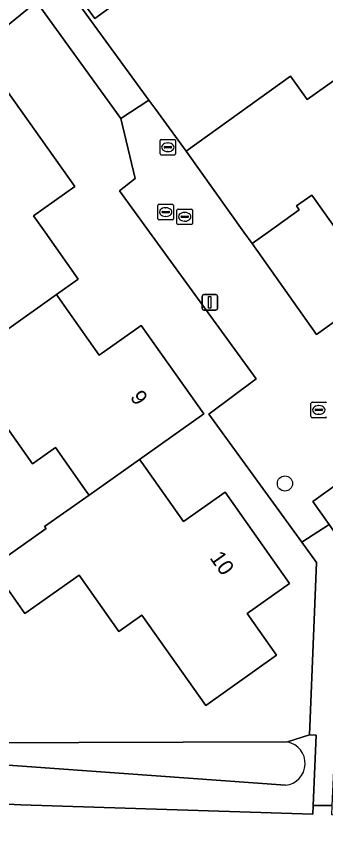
# Model space of a CAD drawing. Extents: x 158455 to 159797, y 387218 to 388672.
# Drawn here: x 159216.9 to 159236.8, y 387710.4 to 387763.8 of the extents above; entities that cross this region are included whole.
import ezdxf

# ---------------------------------------------------------------- set-up
doc = ezdxf.new("R2010")
doc.units = 0
for name, color, linetype in [('IMGEO_Berm_groen', 7, 'Continuous'), ('IMGEO_Boom', 7, 'Continuous'), ('IMGEO_Brandkraan', 7, 'Continuous'), ('IMGEO_Erf', 7, 'Continuous'), ('IMGEO_Kolk', 7, 'Continuous'), ('IMGEO_Lichtmast', 7, 'Continuous'), ('IMGEO_Pand', 7, 'Continuous'), ('IMGEO_Pand_nummerreeks', 7, 'Continuous'), ('IMGEO_Rijbaan_lokaal_open', 7, 'Continuous'), ('IMGEO_Rioolput', 7, 'Continuous'), ('IMGEO_Voetpad_halfverhard', 7, 'Continuous'), ('IMGEO_Voetpad_open', 7, 'Continuous'), ('IMGEO_Waterloop', 7, 'Continuous')]:
    doc.layers.add(name, color=color, linetype=linetype)

msp = doc.modelspace()

# ---------------------------------------------------------------- linework, layer by layer
at = {"layer": 'IMGEO_Berm_groen'}
for points in [[(159197.72, 387744.115), (159197.458, 387744.641), (159197.12, 387744.26), (159196.694, 387743.819), (159197.747, 387742.215), (159196.287, 387741.387), (159199.422, 387735.133), (159203.135, 387727.729), (159203.744, 387726.53), (159209.072, 387716.044), (159215.088, 387713.348), (159215.858, 387713.235), (159217.158, 387713.181), (159235.947, 387712.585), (159235.969, 387713.133), (159236.15, 387717.664), (159235.73, 387717.691), (159234.304, 387717.222)], [(159234.192, 387714.442), (159213.363, 387715.947)]]:
    msp.add_lwpolyline(points, dxfattribs=at)
msp.add_arc((159234.046, 387715.84), 1.406, 275.9436, 79.4423, dxfattribs=at)
at = {"layer": 'IMGEO_Boom'}
msp.add_circle((159234.149, 387733.837), 0.489, dxfattribs=at)
at = {"layer": 'IMGEO_Brandkraan'}
for p, q in [((159226.186, 387755.954), (159227.038, 387755.954)), ((159226.111, 387755.028), (159226.111, 387755.88)), ((159226.37, 387755.448), (159226.37, 387755.46)), ((159226.808, 387755.411), (159226.41, 387755.411)), ((159226.413, 387755.497), (159226.811, 387755.497)), ((159226.599, 387755.734), (159226.624, 387755.734)), ((159226.854, 387755.46), (159226.854, 387755.448)), ((159227.112, 387755.88), (159227.112, 387755.028)), ((159227.038, 387754.954), (159226.186, 387754.954)), ((159226.622, 387755.174), (159226.597, 387755.174))]:
    msp.add_line(p, q, dxfattribs=at)
for points in [[(159226.186, 387755.954), (159227.038, 387755.954)], [(159226.111, 387755.028), (159226.111, 387755.88)], [(159227.112, 387755.88), (159227.112, 387755.028)], [(159227.038, 387754.954), (159226.186, 387754.954)]]:
    msp.add_lwpolyline(points, dxfattribs=at)
for centre, radius, start, end in [((159226.188, 387755.878), 0.0765, 91.552, 178.448), ((159226.188, 387755.878), 0.0765, 91.552, 178.448), ((159227.036, 387755.878), 0.0765, 1.552, 88.448), ((159227.036, 387755.878), 0.0765, 1.552, 88.448), ((159226.41, 387755.457), 0.0403, 85.8775, 175.7526), ((159226.407, 387755.447), 0.0366, 178.938, 274.7102), ((159226.811, 387755.454), 0.043, 264.8664, 352.4533), ((159226.815, 387755.459), 0.0386, 1.7309, 96.639), ((159226.188, 387755.03), 0.0765, 181.552, 268.448), ((159226.188, 387755.03), 0.0765, 181.552, 268.448), ((159227.036, 387755.03), 0.0765, 271.552, 358.448), ((159227.036, 387755.03), 0.0765, 271.552, 358.448)]:
    msp.add_arc(centre, radius, start, end, dxfattribs=at)
for centre, major_axis, ratio, start_param, end_param in [((159226.598, 387755.454), (-0.387, 0.002), 0.722429, 4.712389, 7.853982), ((159226.623, 387755.454), (-0.39, 0.002), 0.717154, 1.570796, 4.712389)]:
    msp.add_ellipse(centre, major_axis=major_axis, ratio=ratio, start_param=start_param, end_param=end_param, dxfattribs=at)
at = {"layer": 'IMGEO_Erf'}
msp.add_lwpolyline([(159224.026, 387765.272), (159221.912, 387763.731), (159220.309, 387765.93), (159222.423, 387767.471)], close=True, dxfattribs=at)
for points in [[(159219.866, 387766.077), (159225.4, 387758.477), (159225.842, 387757.87), (159227.788, 387755.197), (159234.513, 387760.012), (159235.582, 387758.518), (159238.444, 387760.567), (159238.638, 387760.706), (159237.594, 387762.164), (159240.534, 387764.269)], [(159236.179, 387728.753), (159235.227, 387730.066), (159229.26, 387738.298), (159232.294, 387740.557), (159225.442, 387750), (159223.511, 387752.661), (159224.515, 387753.447), (159223.591, 387757.291), (159218.155, 387764.796), (159213.819, 387761.288), (159204.282, 387752.237), (159202.211, 387750), (159197.458, 387744.641), (159197.72, 387744.115)], [(159250.519, 387764.612), (159246.754, 387761.916), (159248.635, 387759.288), (159243.252, 387755.433), (159242.894, 387755.177), (159242.699, 387755.037), (159243.735, 387753.59), (159238.722, 387750), (159237.962, 387749.456), (159237.572, 387750), (159236.047, 387752.13), (159235.872, 387752.374), (159234.896, 387751.676), (159235.071, 387751.431), (159233.071, 387750), (159232.039, 387749.261), (159236.184, 387743.412), (159238.603, 387745.147), (159240.605, 387744.76), (159247.948, 387750), (159265.053, 387762.206), (159265.409, 387764.288)], [(159277.893, 387764.497), (159277.605, 387762.555), (159274.948, 387760.678), (159277.299, 387757.343), (159266.972, 387750), (159257.945, 387743.581), (159255.655, 387746.817), (159253.197, 387745.09), (159251.126, 387745.348), (159238.707, 387736.519), (159238.451, 387734.477), (159235.953, 387732.682), (159236.986, 387731.212), (159238.284, 387729.366), (159238.03, 387721.596), (159240.126, 387721.505), (159241.394, 387720.245), (159241.296, 387717.992), (159237.915, 387718.068), (159237.9, 387717.615), (159239.681, 387717.367), (159366.763, 387713.237)], [(159216.34, 387758.971), (159220.621, 387752.92), (159217.973, 387751.046), (159218.713, 387750), (159220.851, 387746.977), (159219.44, 387745.978), (159219.527, 387745.855), (159222.194, 387742.085), (159224.896, 387743.997), (159228.92, 387738.31), (159224.79, 387735.39), (159224.935, 387735.185), (159227.62, 387731.389), (159230.297, 387733.283), (159234.449, 387727.414), (159231.707, 387725.473), (159233.601, 387722.797), (159229.048, 387719.576), (159224.942, 387725.377), (159223.459, 387724.327), (159220.901, 387727.942), (159217.411, 387725.473), (159215.287, 387728.476), (159218.777, 387730.944), (159218.685, 387731.074), (159221.54, 387733.092), (159221.405, 387733.283), (159219.374, 387736.154), (159217.899, 387735.111), (159213.29, 387741.626)], [(159214.14, 387717.171), (159234.304, 387717.222), (159235.73, 387717.691), (159236.179, 387728.753)]]:
    msp.add_lwpolyline(points, dxfattribs=at)
at = {"layer": 'IMGEO_Kolk'}
for p, q in [((159227.199, 387750.556), (159227.199, 387751.408)), ((159227.274, 387751.482), (159228.126, 387751.482)), ((159227.687, 387751.262), (159227.712, 387751.262)), ((159228.2, 387751.408), (159228.2, 387750.556)), ((159227.458, 387750.976), (159227.458, 387750.988)), ((159227.896, 387750.939), (159227.498, 387750.939)), ((159227.501, 387751.025), (159227.899, 387751.025)), ((159227.71, 387750.702), (159227.685, 387750.702)), ((159227.942, 387750.988), (159227.942, 387750.976)), ((159228.126, 387750.482), (159227.274, 387750.482))]:
    msp.add_line(p, q, dxfattribs=at)
for points in [[(159227.199, 387750.556), (159227.199, 387751.408)], [(159227.274, 387751.482), (159228.126, 387751.482)], [(159228.2, 387751.408), (159228.2, 387750.556)], [(159228.126, 387750.482), (159227.274, 387750.482)]]:
    msp.add_lwpolyline(points, dxfattribs=at)
for centre, radius, start, end in [((159227.276, 387751.406), 0.0765, 91.552, 178.448), ((159227.276, 387751.406), 0.0765, 91.552, 178.448), ((159228.124, 387751.406), 0.0765, 1.552, 88.448), ((159228.124, 387751.406), 0.0765, 1.552, 88.448), ((159227.498, 387750.985), 0.0403, 85.8775, 175.7526), ((159227.495, 387750.975), 0.0366, 178.938, 274.7102), ((159227.899, 387750.982), 0.043, 264.8664, 352.4533), ((159227.903, 387750.987), 0.0386, 1.7309, 96.639), ((159227.276, 387750.558), 0.0765, 181.552, 268.448), ((159227.276, 387750.558), 0.0765, 181.552, 268.448), ((159228.124, 387750.558), 0.0765, 271.552, 358.448), ((159228.124, 387750.558), 0.0765, 271.552, 358.448)]:
    msp.add_arc(centre, radius, start, end, dxfattribs=at)
for centre, major_axis, ratio, start_param, end_param in [((159227.686, 387750.982), (-0.387, 0.002), 0.722429, 4.712389, 7.853982), ((159227.711, 387750.982), (-0.39, 0.002), 0.717154, 1.570796, 4.712389)]:
    msp.add_ellipse(centre, major_axis=major_axis, ratio=ratio, start_param=start_param, end_param=end_param, dxfattribs=at)
at = {"layer": 'IMGEO_Lichtmast'}
for p, q in [((159228.819, 387745.083), (159228.819, 387745.883)), ((159228.819, 387745.883), (159228.819, 387745.083)), ((159228.919, 387745.983), (159229.709, 387745.983)), ((159229.709, 387745.983), (159228.919, 387745.983)), ((159229.809, 387745.883), (159229.809, 387745.083)), ((159229.809, 387745.083), (159229.809, 387745.883)), ((159229.709, 387744.983), (159228.919, 387744.983)), ((159228.919, 387744.983), (159229.709, 387744.983))]:
    msp.add_line(p, q, dxfattribs=at)
msp.add_lwpolyline([(159229.239, 387745.858), (159229.389, 387745.858), (159229.389, 387745.108), (159229.239, 387745.108), (159229.239, 387745.858)], dxfattribs=at)
for centre, start, end in [((159228.919, 387745.883), 90, 180), ((159228.919, 387745.883), 90, 180), ((159229.709, 387745.883), 0, 90), ((159229.709, 387745.883), 360, 90), ((159228.919, 387745.083), 180, 270), ((159228.919, 387745.083), 180, 270), ((159229.709, 387745.083), 270, 0), ((159229.709, 387745.083), 270, 0)]:
    msp.add_arc(centre, 0.1, start, end, dxfattribs=at)
at = {"layer": 'IMGEO_Pand'}
for points in [[(159220.309, 387765.93), (159221.912, 387763.731), (159224.026, 387765.272), (159222.423, 387767.471)], [(159238.638, 387760.706), (159238.444, 387760.567), (159235.582, 387758.518), (159234.513, 387760.012), (159227.788, 387755.197), (159231.51, 387750), (159232.039, 387749.261), (159233.071, 387750), (159235.071, 387751.431), (159234.896, 387751.676), (159235.872, 387752.374), (159236.047, 387752.13), (159237.572, 387750), (159237.962, 387749.456), (159238.722, 387750), (159243.735, 387753.59), (159242.699, 387755.037)], [(159217.973, 387751.046), (159220.621, 387752.92), (159216.34, 387758.971), (159209.096, 387753.846), (159206.13, 387751.748), (159208.321, 387748.651), (159213.29, 387741.626), (159219.44, 387745.978), (159220.851, 387746.977), (159218.713, 387750)], [(159219.527, 387745.855), (159219.44, 387745.978), (159213.29, 387741.626), (159217.899, 387735.111), (159219.374, 387736.154), (159221.405, 387733.283), (159221.54, 387733.092), (159224.79, 387735.39), (159228.92, 387738.31), (159224.896, 387743.997), (159222.194, 387742.085)], [(159230.297, 387733.283), (159227.62, 387731.389), (159224.935, 387735.185), (159224.79, 387735.39), (159221.54, 387733.092), (159218.685, 387731.074), (159218.777, 387730.944), (159215.287, 387728.476), (159217.411, 387725.473), (159220.901, 387727.942), (159223.459, 387724.327), (159224.942, 387725.377), (159229.048, 387719.576), (159233.601, 387722.797), (159231.707, 387725.473), (159234.449, 387727.414)]]:
    msp.add_lwpolyline(points, close=True, dxfattribs=at)
at = {"layer": 'IMGEO_Rijbaan_lokaal_open'}
msp.add_lwpolyline([(159238.603, 387745.147), (159236.184, 387743.412), (159232.039, 387749.261), (159231.51, 387750), (159227.788, 387755.197), (159225.842, 387757.87), (159225.4, 387758.477), (159223.591, 387757.291), (159224.515, 387753.447), (159223.511, 387752.661), (159225.442, 387750), (159232.294, 387740.557), (159229.26, 387738.298), (159235.227, 387730.066), (159236.986, 387731.212), (159235.953, 387732.682), (159238.451, 387734.477)], dxfattribs=at)
at = {"layer": 'IMGEO_Rioolput'}
for p, q in [((159225.977, 387750.857), (159225.977, 387751.709)), ((159226.052, 387751.783), (159226.904, 387751.783)), ((159226.978, 387751.709), (159226.978, 387750.857)), ((159226.236, 387751.277), (159226.236, 387751.289)), ((159226.674, 387751.24), (159226.276, 387751.24)), ((159226.279, 387751.326), (159226.677, 387751.326)), ((159226.465, 387751.563), (159226.49, 387751.563)), ((159226.72, 387751.289), (159226.72, 387751.277)), ((159226.904, 387750.783), (159226.052, 387750.783)), ((159226.488, 387751.003), (159226.463, 387751.003)), ((159235.825, 387738.141), (159235.825, 387738.993)), ((159235.9, 387739.067), (159236.752, 387739.067)), ((159236.084, 387738.561), (159236.084, 387738.573)), ((159236.522, 387738.524), (159236.124, 387738.524)), ((159236.127, 387738.61), (159236.525, 387738.61)), ((159236.313, 387738.847), (159236.338, 387738.847)), ((159236.568, 387738.573), (159236.568, 387738.561)), ((159236.752, 387738.067), (159235.9, 387738.067)), ((159236.336, 387738.287), (159236.311, 387738.287))]:
    msp.add_line(p, q, dxfattribs=at)
for points in [[(159225.977, 387750.857), (159225.977, 387751.709)], [(159226.052, 387751.783), (159226.904, 387751.783)], [(159226.978, 387751.709), (159226.978, 387750.857)], [(159226.904, 387750.783), (159226.052, 387750.783)], [(159235.825, 387738.141), (159235.825, 387738.993)], [(159235.9, 387739.067), (159236.752, 387739.067)], [(159236.752, 387738.067), (159235.9, 387738.067)]]:
    msp.add_lwpolyline(points, dxfattribs=at)
for centre, radius, start, end in [((159226.054, 387751.707), 0.0765, 91.552, 178.448), ((159226.054, 387751.707), 0.0765, 91.552, 178.448), ((159226.902, 387751.707), 0.0765, 1.552, 88.448), ((159226.902, 387751.707), 0.0765, 1.552, 88.448), ((159226.276, 387751.286), 0.0403, 85.8775, 175.7526), ((159226.273, 387751.276), 0.0366, 178.938, 274.7102), ((159226.677, 387751.283), 0.043, 264.8664, 352.4533), ((159226.681, 387751.288), 0.0386, 1.7309, 96.639), ((159226.054, 387750.859), 0.0765, 181.552, 268.448), ((159226.054, 387750.859), 0.0765, 181.552, 268.448), ((159226.902, 387750.859), 0.0765, 271.552, 358.448), ((159226.902, 387750.859), 0.0765, 271.552, 358.448), ((159235.902, 387738.991), 0.0765, 91.552, 178.448), ((159235.902, 387738.991), 0.0765, 91.552, 178.448), ((159236.75, 387738.991), 0.0765, 1.552, 88.448), ((159236.75, 387738.991), 0.0765, 1.552, 88.448), ((159236.124, 387738.57), 0.0403, 85.8775, 175.7526), ((159236.121, 387738.56), 0.0366, 178.938, 274.7102), ((159236.525, 387738.567), 0.043, 264.8664, 352.4533), ((159236.529, 387738.572), 0.0386, 1.7309, 96.639), ((159235.902, 387738.143), 0.0765, 181.552, 268.448), ((159235.902, 387738.143), 0.0765, 181.552, 268.448), ((159236.75, 387738.143), 0.0765, 271.552, 358.448), ((159236.75, 387738.143), 0.0765, 271.552, 358.448)]:
    msp.add_arc(centre, radius, start, end, dxfattribs=at)
for centre, major_axis, ratio, start_param, end_param in [((159226.464, 387751.283), (-0.387, 0.002), 0.722429, 4.712389, 7.853982), ((159226.489, 387751.283), (-0.39, 0.002), 0.717154, 1.570796, 4.712389), ((159236.312, 387738.567), (-0.387, 0.002), 0.722429, 4.712389, 7.853982), ((159236.337, 387738.567), (-0.39, 0.002), 0.717154, 1.570796, 4.712389)]:
    msp.add_ellipse(centre, major_axis=major_axis, ratio=ratio, start_param=start_param, end_param=end_param, dxfattribs=at)
at = {"layer": 'IMGEO_Voetpad_halfverhard'}
msp.add_lwpolyline([(159440.368, 387706.497), (159440.403, 387707.122), (159439.155, 387707.164), (159439.115, 387706.535), (159433.346, 387706.713), (159386.156, 387708.167), (159372.279, 387708.595), (159372.194, 387709.441), (159371.015, 387709.344), (159371.1, 387708.633), (159337.222, 387709.784), (159261.348, 387711.686), (159237.161, 387712.542), (159237.189, 387713.141), (159235.969, 387713.133), (159235.947, 387712.585), (159217.158, 387713.181), (159215.858, 387713.235), (159215.088, 387713.348), (159209.072, 387716.044), (159214.062, 387706.489), (159214.378, 387707.16), (159215.755, 387708.691), (159216.346, 387709.347)], dxfattribs=at)
at = {"layer": 'IMGEO_Voetpad_open'}
msp.add_lwpolyline([(159195.41, 387742.999), (159196.287, 387741.387), (159197.747, 387742.215), (159196.694, 387743.819), (159197.12, 387744.26), (159197.458, 387744.641), (159202.211, 387750), (159204.282, 387752.237), (159213.819, 387761.288), (159218.155, 387764.796), (159219.866, 387766.077), (159303.107, 387825.734), (159307.132, 387828.619), (159309.204, 387832.674)], dxfattribs=at)
for points in [[(159219.866, 387766.077), (159218.155, 387764.796), (159223.591, 387757.291), (159225.4, 387758.477)], [(159238.284, 387729.366), (159236.986, 387731.212), (159235.227, 387730.066), (159236.179, 387728.753), (159235.73, 387717.691), (159236.15, 387717.664), (159235.969, 387713.133), (159237.189, 387713.141), (159237.4, 387717.632), (159237.9, 387717.615), (159237.915, 387718.068), (159237.832, 387718.07), (159237.985, 387721.598), (159238.03, 387721.596)]]:
    msp.add_lwpolyline(points, close=True, dxfattribs=at)
at = {"layer": 'IMGEO_Waterloop'}
for points in [[(159234.304, 387717.222), (159214.14, 387717.171)], [(159213.363, 387715.947), (159234.192, 387714.442)]]:
    msp.add_lwpolyline(points, dxfattribs=at)
msp.add_arc((159234.046, 387715.84), 1.406, 275.9436, 79.4423, dxfattribs=at)

# ---------------------------------------------------------------- texts
at = {"layer": 'IMGEO_Pand_nummerreeks'}
for s, rotation, p in [('9', 305.2825, (159224.144, 387739.382)), ('10', 305.2768, (159229.273, 387729.053))]:
    msp.add_text(s, height=1, rotation=rotation, dxfattribs=at).set_placement(p)

doc.saveas('drawing.dxf')
